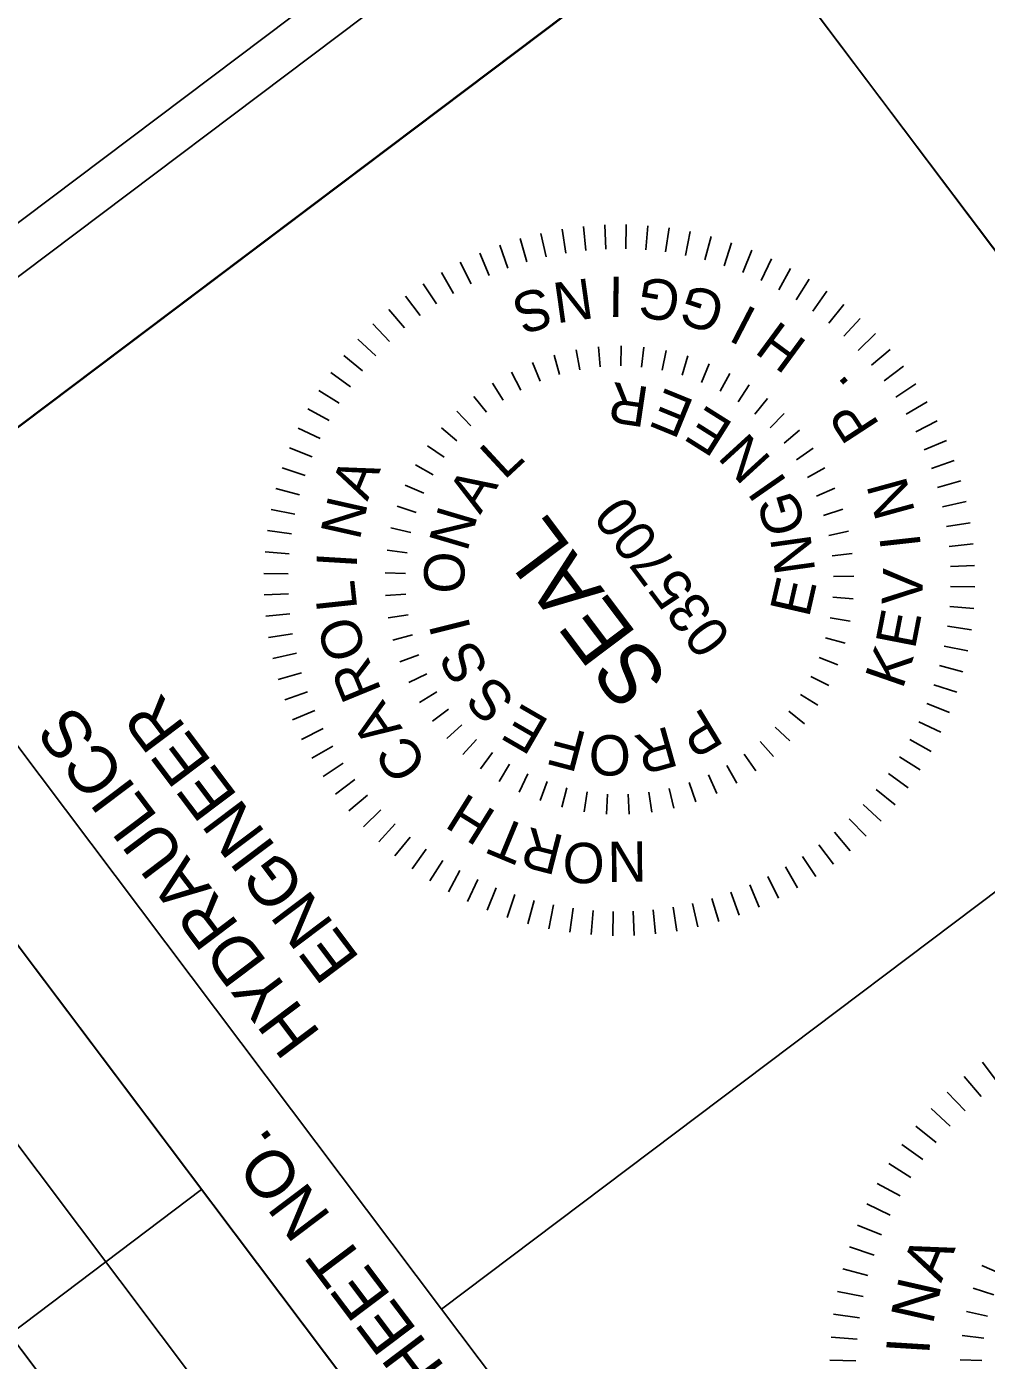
# Model space of a CAD drawing. Extents: x 1262337 to 1264328, y 775525 to 777528.
# Drawn here: x 1262516 to 1262616.1, y 776806.7 to 776945.7 of the extents above; entities that cross this region are included whole.
import ezdxf

# ---------------------------------------------------------------- set-up
doc = ezdxf.new("R2010")
doc.units = 0
for name, color, linetype in [('Default', 7, 'Continuous'), ('Raster_Level_0', 7, 'Continuous'), ('Sheet Plan CELL', 7, 'Continuous'), ('Sheet Plan Layout CELL', 7, 'Continuous'), ('Sheet Plot Border Inside CELL', 7, 'Continuous'), ('Sheet Plot Border Outside CELL', 7, 'Continuous')]:
    doc.layers.add(name, color=color, linetype=linetype)

# ---------------------------------------------------------------- blocks, each defined once
blk = doc.blocks.new('SEALNC2')
at = {"layer": 'Default'}
for p, q in [((0.5431, 0.6107), (0.5087, 0.5669)), ((0.581, 0.579), (0.544, 0.5374)), ((0.6169, 0.5452), (0.5775, 0.5058)), ((0.6507, 0.5092), (0.609, 0.4723)), ((0.6823, 0.4712), (0.6385, 0.4369)), ((0.7116, 0.4314), (0.6657, 0.3998)), ((0.3761, 0.3874), (0.347, 0.3512)), ((0.7383, 0.39), (0.6906, 0.3611)), ((0.415, 0.3529), (0.3825, 0.3196)), ((0.7626, 0.3469), (0.7132, 0.321)), ((0.4505, 0.3147), (0.415, 0.2848)), ((0.7841, 0.3024), (0.7333, 0.2797)), ((0.4821, 0.2734), (0.4438, 0.2469)), ((0.803, 0.2568), (0.7509, 0.2371)), ((0.5094, 0.2291), (0.4689, 0.2065)), ((0.8191, 0.2102), (0.7658, 0.1937)), ((0.8323, 0.1625), (0.7782, 0.1493)), ((0.8426, 0.1143), (0.7878, 0.1043)), ((0.8499, 0.0655), (0.7947, 0.0588)), ((0.8544, 0.0163), (0.7988, 0.013)), ((0.8558, -0.0331), (0.8001, -0.033))]:
    blk.add_line(p, q, dxfattribs=at)
for s, rotation, p in [('I', 319.5261, (0.4234, 0.4346)), ('N', 310.2316, (0.4699, 0.3908)), ('A', 300.4641, (0.531, 0.3222))]:
    blk.add_text(s, height=0.0928, rotation=rotation, dxfattribs=at).set_placement(p)

msp = doc.modelspace()

# ---------------------------------------------------------------- linework, layer by layer
at = {"layer": 'Default'}
for p, q in [((1262709.29, 776799.84), (1262588.97, 776959.58)), ((1262569.64, 776924.17), (1262570.2, 776921.71)), ((1262571.84, 776924.6), (1262572.25, 776922.11)), ((1262574.06, 776924.9), (1262574.31, 776922.39)), ((1262576.29, 776925.06), (1262576.4, 776922.54)), ((1262578.53, 776925.08), (1262578.48, 776922.56)), ((1262580.77, 776924.97), (1262580.57, 776922.46)), ((1262582.99, 776924.73), (1262582.64, 776922.23)), ((1262585.2, 776924.35), (1262584.7, 776921.87)), ((1262587.38, 776923.84), (1262586.73, 776921.4)), ((1262565.35, 776922.93), (1262566.2, 776920.55)), ((1262567.47, 776923.62), (1262568.18, 776921.19)), ((1262589.52, 776923.2), (1262588.73, 776920.8)), ((1262561.23, 776921.17), (1262562.36, 776918.91)), ((1262563.26, 776922.11), (1262564.26, 776919.79)), ((1262591.62, 776922.43), (1262590.69, 776920.08)), ((1262593.68, 776921.53), (1262592.6, 776919.25)), ((1262559.26, 776920.1), (1262560.53, 776917.92)), ((1262595.67, 776920.51), (1262594.45, 776918.3)), ((1262557.36, 776918.92), (1262558.75, 776916.82)), ((1262597.6, 776919.38), (1262596.25, 776917.24)), ((1262555.53, 776917.63), (1262557.05, 776915.61)), ((1262599.45, 776918.13), (1262597.98, 776916.07)), ((1262553.78, 776916.23), (1262555.42, 776914.31)), ((1262601.23, 776916.76), (1262599.64, 776914.81)), ((1262552.13, 776914.73), (1262553.87, 776912.91)), ((1262602.93, 776915.3), (1262601.21, 776913.44)), ((1262550.56, 776913.13), (1262552.42, 776911.42)), ((1262604.52, 776913.73), (1262602.7, 776911.98)), ((1262549.09, 776911.44), (1262551.05, 776909.84)), ((1262571.01, 776911.49), (1262571.59, 776909.46)), ((1262573.3, 776912.03), (1262573.69, 776909.96)), ((1262575.63, 776912.36), (1262575.83, 776910.26)), ((1262578, 776912.46), (1262577.98, 776910.35)), ((1262580.35, 776912.32), (1262580.14, 776910.23)), ((1262582.68, 776911.97), (1262582.27, 776909.9)), ((1262584.97, 776911.39), (1262584.36, 776909.38)), ((1262606.03, 776912.08), (1262604.1, 776910.44)), ((1262568.77, 776910.72), (1262569.55, 776908.76)), ((1262587.19, 776910.59), (1262586.38, 776908.64)), ((1262607.43, 776910.33), (1262605.41, 776908.81)), ((1262547.73, 776909.66), (1262549.78, 776908.18)), ((1262564.58, 776908.55), (1262565.72, 776906.79)), ((1262567.53, 776907.83), (1262566.56, 776909.7)), ((1262589.33, 776909.58), (1262588.33, 776907.72)), ((1262546.48, 776907.8), (1262548.62, 776906.46)), ((1262562.66, 776907.18), (1262563.97, 776905.53)), ((1262591.35, 776908.37), (1262590.19, 776906.61)), ((1262608.72, 776908.5), (1262606.62, 776907.1)), ((1262545.35, 776905.87), (1262547.56, 776904.66)), ((1262593.25, 776906.97), (1262591.92, 776905.33)), ((1262609.9, 776906.6), (1262607.72, 776905.33)), ((1262560.89, 776905.63), (1262562.34, 776904.11)), ((1262595.01, 776905.39), (1262593.53, 776903.9)), ((1262610.96, 776904.63), (1262608.71, 776903.5)), ((1262544.33, 776903.88), (1262546.61, 776902.8)), ((1262559.27, 776903.91), (1262560.87, 776902.54)), ((1262596.61, 776903.65), (1262594.98, 776902.31)), ((1262543.43, 776901.83), (1262545.78, 776900.89)), ((1262557.82, 776902.04), (1262559.55, 776900.83)), ((1262598.02, 776901.77), (1262596.29, 776900.58)), ((1262611.9, 776902.6), (1262609.58, 776901.6)), ((1262612.72, 776900.51), (1262610.34, 776899.66)), ((1262542.66, 776899.73), (1262545.06, 776898.93)), ((1262556.56, 776900.05), (1262558.4, 776899.01)), ((1262599.25, 776899.75), (1262597.41, 776898.74)), ((1262542.02, 776897.58), (1262544.46, 776896.93)), ((1262555.5, 776897.94), (1262557.43, 776897.09)), ((1262598.36, 776896.79), (1262600.29, 776897.62)), ((1262613.41, 776898.38), (1262610.98, 776897.68)), ((1262613.97, 776896.22), (1262611.51, 776895.66)), ((1262541.51, 776895.4), (1262543.98, 776894.9)), ((1262554.65, 776895.74), (1262556.65, 776895.08)), ((1262601.11, 776895.42), (1262599.1, 776894.78)), ((1262554.01, 776893.47), (1262556.07, 776893)), ((1262614.4, 776894.02), (1262611.91, 776893.61)), ((1262541.13, 776893.2), (1262543.63, 776892.84)), ((1262601.71, 776893.14), (1262599.65, 776892.7)), ((1262540.88, 776890.97), (1262543.4, 776890.77)), ((1262553.6, 776891.14), (1262555.69, 776890.87)), ((1262602.09, 776890.81), (1262600, 776890.57)), ((1262614.7, 776891.8), (1262612.18, 776891.54)), ((1262614.85, 776889.57), (1262612.33, 776889.46)), ((1262540.77, 776888.73), (1262543.3, 776888.69)), ((1262553.41, 776888.79), (1262555.52, 776888.73)), ((1262602.25, 776888.45), (1262600.14, 776888.42)), ((1262540.8, 776886.5), (1262543.32, 776886.6)), ((1262553.45, 776886.43), (1262555.56, 776886.57)), ((1262614.88, 776887.33), (1262612.35, 776887.38)), ((1262602.18, 776886.09), (1262600.08, 776886.26)), ((1262614.77, 776885.09), (1262612.25, 776885.29)), ((1262540.96, 776884.27), (1262543.47, 776884.52)), ((1262553.72, 776884.09), (1262555.8, 776884.43)), ((1262601.87, 776883.75), (1262599.8, 776884.12)), ((1262541.25, 776882.04), (1262543.75, 776882.45)), ((1262554.21, 776881.78), (1262556.25, 776882.32)), ((1262614.52, 776882.87), (1262612.02, 776883.22)), ((1262601.35, 776881.45), (1262599.32, 776882.02)), ((1262614.15, 776880.66), (1262611.67, 776881.16)), ((1262541.69, 776879.85), (1262544.15, 776880.41)), ((1262554.93, 776879.53), (1262556.9, 776880.26)), ((1262600.6, 776879.21), (1262598.64, 776879.97)), ((1262542.24, 776877.68), (1262544.67, 776878.38)), ((1262555.86, 776877.36), (1262557.75, 776878.28)), ((1262599.64, 776877.06), (1262597.76, 776878)), ((1262613.63, 776878.48), (1262611.19, 776879.13)), ((1262612.99, 776876.34), (1262610.6, 776877.13)), ((1262542.93, 776875.55), (1262545.31, 776876.4)), ((1262556.99, 776875.29), (1262558.78, 776876.39)), ((1262598.49, 776875), (1262596.71, 776876.12)), ((1262543.75, 776873.46), (1262546.07, 776874.46)), ((1262558.32, 776873.34), (1262560, 776874.6)), ((1262560, 776874.6), (1262558.32, 776873.34)), ((1262597.13, 776873.07), (1262595.47, 776874.36)), ((1262612.22, 776874.24), (1262609.88, 776875.17)), ((1262544.69, 776871.43), (1262546.95, 776872.57)), ((1262559.83, 776871.52), (1262561.38, 776872.94)), ((1262595.6, 776871.28), (1262594.07, 776872.72)), ((1262611.33, 776872.18), (1262609.04, 776873.26)), ((1262561.5, 776869.86), (1262562.91, 776871.43)), ((1262593.9, 776869.64), (1262592.51, 776871.22)), ((1262610.31, 776870.19), (1262608.1, 776871.41)), ((1262545.75, 776869.47), (1262547.94, 776870.73)), ((1262563.33, 776868.37), (1262564.58, 776870.07)), ((1262592.05, 776868.17), (1262590.82, 776869.88)), ((1262546.93, 776867.56), (1262549.04, 776868.96)), ((1262565.3, 776867.06), (1262566.38, 776868.87)), ((1262590.06, 776866.89), (1262589.01, 776868.71)), ((1262609.17, 776868.26), (1262607.03, 776869.61)), ((1262548.23, 776865.73), (1262550.24, 776867.25)), ((1262567.38, 776865.95), (1262568.28, 776867.85)), ((1262569.56, 776865.05), (1262570.28, 776867.03)), ((1262585.78, 776864.94), (1262585.09, 776866.93)), ((1262587.97, 776865.81), (1262587.09, 776867.73)), ((1262607.92, 776866.4), (1262605.87, 776867.88)), ((1262549.63, 776863.99), (1262551.55, 776865.62)), ((1262571.82, 776864.36), (1262572.34, 776866.4)), ((1262574.13, 776863.89), (1262574.45, 776865.97)), ((1262576.48, 776863.64), (1262576.59, 776865.74)), ((1262578.84, 776863.63), (1262578.75, 776865.73)), ((1262581.19, 776863.84), (1262580.9, 776865.92)), ((1262583.51, 776864.28), (1262583.02, 776866.32)), ((1262606.56, 776864.62), (1262604.6, 776866.22)), ((1262551.13, 776862.33), (1262552.95, 776864.08)), ((1262605.1, 776862.93), (1262603.24, 776864.64)), ((1262603.53, 776861.34), (1262601.78, 776863.15)), ((1262552.73, 776860.76), (1262554.44, 776862.62)), ((1262601.87, 776859.83), (1262600.23, 776861.75)), ((1262554.42, 776859.3), (1262556.02, 776861.25)), ((1262556.2, 776857.93), (1262557.68, 776859.99)), ((1262600.12, 776858.43), (1262598.6, 776860.45)), ((1262558.05, 776856.69), (1262559.4, 776858.83)), ((1262598.29, 776857.14), (1262596.9, 776859.24)), ((1262559.99, 776855.55), (1262561.2, 776857.76)), ((1262594.42, 776854.9), (1262593.29, 776857.15)), ((1262596.39, 776855.96), (1262595.13, 776858.14)), ((1262561.98, 776854.53), (1262563.06, 776856.82)), ((1262564.03, 776853.63), (1262564.97, 776855.98)), ((1262592.39, 776853.95), (1262591.4, 776856.27)), ((1262566.13, 776852.87), (1262566.93, 776855.26)), ((1262568.27, 776852.22), (1262568.93, 776854.66)), ((1262586.01, 776851.89), (1262585.45, 776854.35)), ((1262588.18, 776852.45), (1262587.47, 776854.87)), ((1262590.31, 776853.13), (1262589.45, 776855.52)), ((1262570.46, 776851.71), (1262570.96, 776854.19)), ((1262572.66, 776851.34), (1262573.01, 776853.83)), ((1262574.89, 776851.09), (1262575.09, 776853.61)), ((1262577.13, 776850.98), (1262577.17, 776853.5)), ((1262579.36, 776851), (1262579.26, 776853.53)), ((1262581.59, 776851.16), (1262581.34, 776853.68)), ((1262583.81, 776851.46), (1262583.41, 776853.95))]:
    msp.add_line(p, q, dxfattribs=at)
at = {"layer": 'Raster_Level_0'}
for points in [[(1262559.28, 776812.07), (1262499.13, 776891.92), (1262588.97, 776959.59), (1262649.11, 776879.74)], [(1262619.45, 776732.18), (1262559.28, 776812.07), (1262649.11, 776879.74), (1262709.29, 776799.84)]]:
    msp.add_lwpolyline(points, close=True, dxfattribs=at)
at = {"layer": 'Sheet Plan CELL'}
for p, q in [((1262609.52, 776724.64), (1262489.15, 776884.41)), ((1262609.52, 776724.64), (1262489.15, 776884.41)), ((1262599.51, 776717.08), (1262479.17, 776876.89)), ((1262514.33, 776809.45), (1262534.27, 776824.53))]:
    msp.add_line(p, q, dxfattribs=at)
for points in [[(1262469.12, 776869.36), (1263371.6, 775671.18), (1264210.31, 776302.91), (1263307.84, 777501.07)], [(1262589.48, 776709.54), (1262469.12, 776869.36), (1262489.15, 776884.41), (1262609.52, 776724.64)]]:
    msp.add_lwpolyline(points, close=True, dxfattribs=at)
at = {"layer": 'Sheet Plan Layout CELL'}
msp.add_lwpolyline([(1262782.01, 776805.47), (1262638.06, 776996.59), (1262469.11, 776869.37), (1262613.08, 776678.23)], close=True, dxfattribs=at)
at = {"layer": 'Sheet Plot Border Inside CELL'}
msp.add_lwpolyline([(1264304.66, 776181.82), (1263302.32, 777512.55), (1262459.63, 776877.83), (1263461.96, 775547.09)], close=True, dxfattribs=at)
at = {"layer": 'Sheet Plot Border Outside CELL'}
msp.add_lwpolyline([(1264328.45, 776183.46), (1263315.59, 777528.19), (1262440.94, 776869.39), (1263453.8, 775524.67)], close=True, dxfattribs=at)

# ---------------------------------------------------------------- block references
at = {"layer": 'Default', "xscale": 48.735525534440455, "yscale": 48.73552553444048, "rotation": 126.9874160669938}
msp.add_blockref('SEALNC2', (1262639.46, 776803.51), dxfattribs=at)

# ---------------------------------------------------------------- texts
at = {"layer": 'Default'}
for s, height, rotation, p in [('S', 4.21, 196.6613, (1262570, 776918.69)), ('N', 4.21, 187.9885, (1262574.71, 776919.52)), ('I', 4.21, 179.1959, (1262578.27, 776919.65)), ('G', 4.21, 170.3133, (1262584.42, 776918.98)), ('G', 4.21, 161.4307, (1262589.12, 776917.59)), ('I', 4.21, 152.608, (1262592.37, 776916.1)), ('H', 4.21, 143.6055, (1262597.55, 776912.77)), ('R', 4.21, 171.5538, (1262581.06, 776908.11)), ('.', 4.21, 130.8212, (1262601.97, 776908.45)), ('E', 4.21, 157.7827, (1262585.81, 776906.67)), ('E', 4.21, 147.7968, (1262589.84, 776904.3)), ('P', 4.21, 123.0788, (1262605.03, 776904.2)), ('N', 4.21, 132.4047, (1262593.8, 776900.61)), ('L', 4.21, 42.8595, (1262565.81, 776898.39)), ('A', 4.21, 67.506, (1262551.54, 776896.18)), ('A', 4.21, 58.1558, (1262563.3, 776894.79)), ('I', 4.21, 124.7751, (1262595.4, 776898.25)), ('N', 4.21, 105.2835, (1262608.67, 776895.12)), ('N', 4.21, 77.2735, (1262550.73, 776892.09)), ('035700', 4.206, 126.9889, (1262589.6, 776882.12)), ('G', 4.21, 106.6803, (1262597.34, 776893.43)), ('N', 4.21, 73.452, (1262561.93, 776890.88)), ('SEAL', 6.315, 126.9889, (1262583.12, 776877.85)), ('N', 4.21, 97.914, (1262598.25, 776888.96)), ('I', 4.21, 96.311, (1262609.26, 776891.5)), ('I', 4.21, 86.568, (1262550.42, 776889.21)), ('O', 4.21, 88.7483, (1262561.63, 776886.59)), ('V', 4.21, 87.6384, (1262609.36, 776885.37)), ('L', 4.21, 96.1434, (1262550.51, 776885.03)), ('E', 4.21, 77.059, (1262597.57, 776884.03)), ('O', 4.21, 109.2797, (1262551.58, 776880.49)), ('I', 4.21, 104.0445, (1262562.37, 776882.9)), ('E', 4.21, 78.9957, (1262608.62, 776880.74)), ('S', 4.21, 119.3407, (1262564.33, 776878.78)), ('K', 4.21, 70.9239, (1262607.32, 776876.57)), ('R', 4.21, 112.3365, (1262553.07, 776876.5)), ('S', 4.21, 134.637, (1262567.14, 776875.64)), ('A', 4.21, 124.3458, (1262555.26, 776872.57)), ('E', 4.21, 149.9332, (1262570.67, 776873.35)), ('P', 4.21, 211.1182, (1262586.72, 776874.84)), ('R', 4.21, 195.822, (1262583.01, 776872.84)), ('C', 4.21, 124.3458, (1262557.95, 776868.85)), ('F', 4.21, 165.2295, (1262574.6, 776872.09)), ('O', 4.21, 180.5257, (1262578.99, 776871.9)), ('H', 4.21, 148.0565, (1262565.15, 776863.79)), ('T', 4.21, 157.4885, (1262568.65, 776862.19)), ('R', 4.21, 165.6494, (1262572.23, 776861.34)), ('O', 4.21, 178.7062, (1262576.33, 776860.61)), ('N', 4.21, 180.6656, (1262580.62, 776860.82))]:
    msp.add_text(s, height=height, rotation=rotation, dxfattribs=at).set_placement(p)
at = {"layer": 'Raster_Level_0'}
for s, height, p in [('ENGINEER', 4.999, (1262550.86, 776848.59)), ('HYDRAULICS', 4.999, (1262546.79, 776840.78)), ('R/W SHEET NO.', 4.9986, (1262571.34, 776790.57))]:
    msp.add_text(s, height=height, rotation=126.9874, dxfattribs=at).set_placement(p)

doc.saveas('drawing.dxf')
